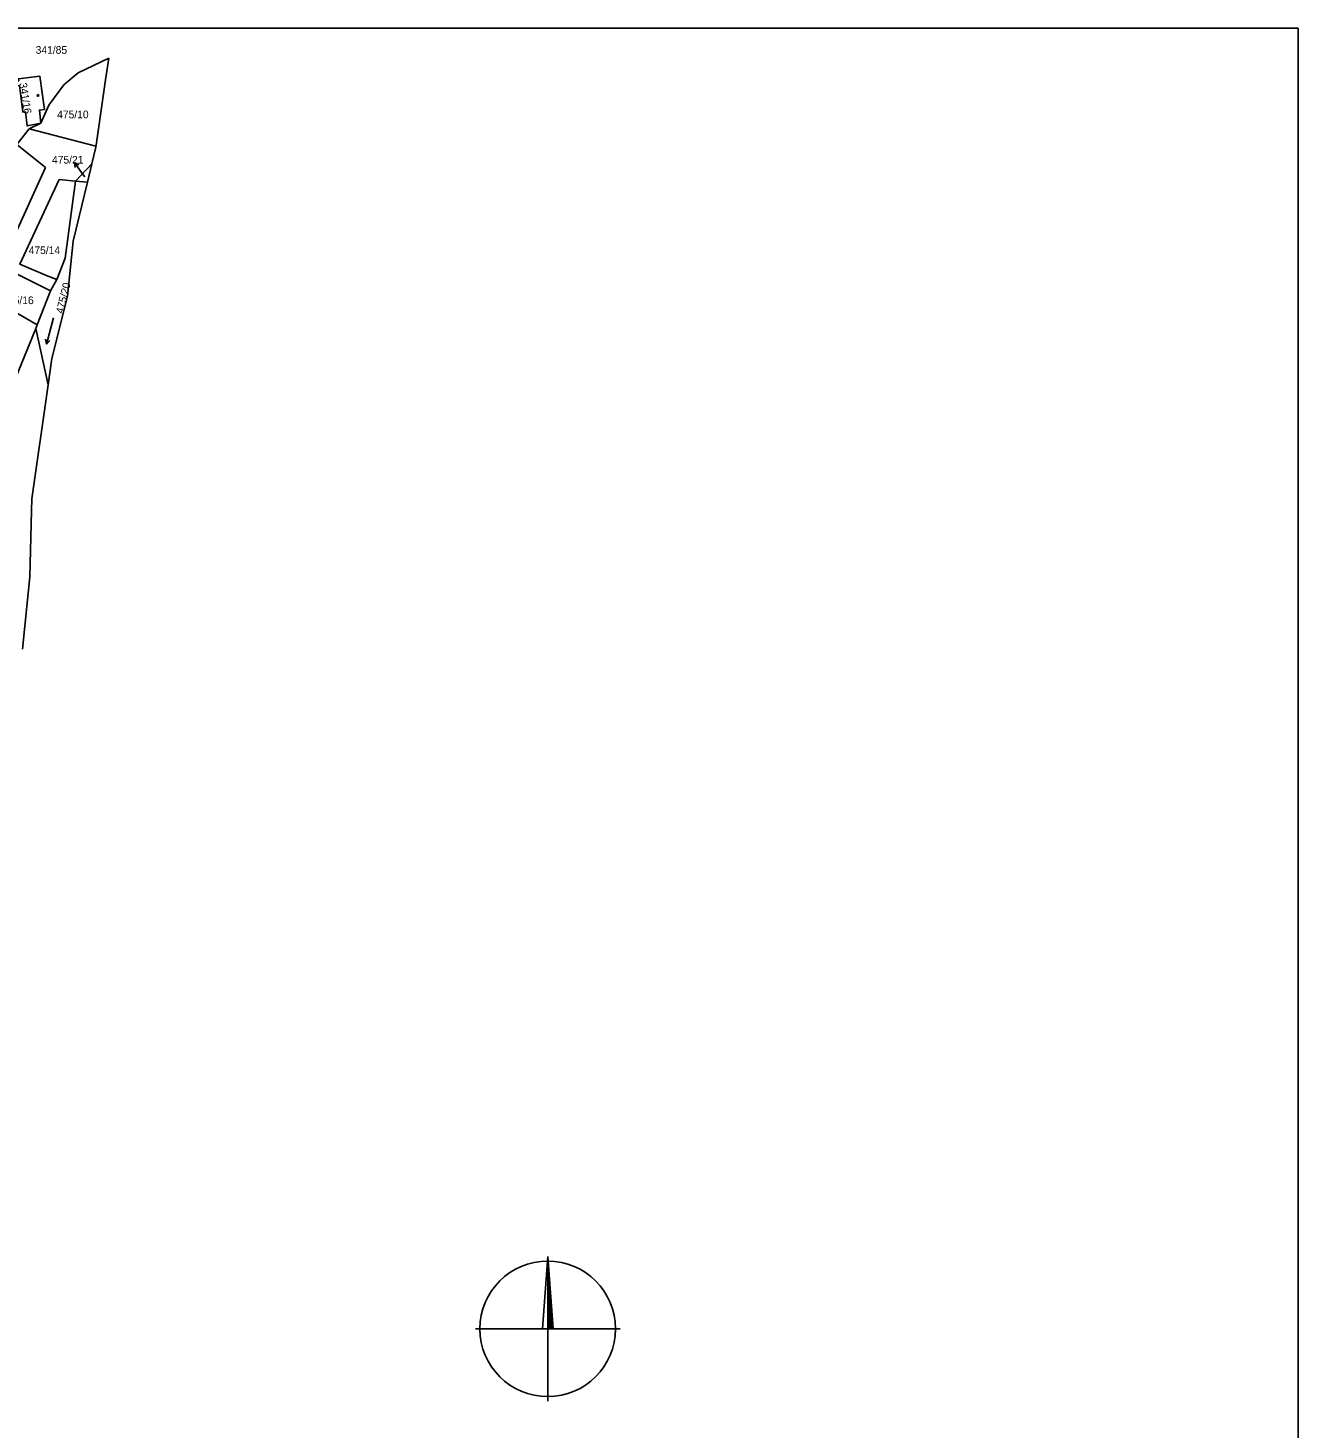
# Model space of a CAD drawing. Extents: x -558358 to -557517, y -1073785 to -1073189.
# Drawn here: x -557797.5 to -557516.5, y -1073499.8 to -1073190.1 of the extents above; entities that cross this region are included whole.
import ezdxf

# ---------------------------------------------------------------- set-up
doc = ezdxf.new("R2010")
doc.units = 0
for name, color, linetype in [('Hranice parcel', 7, 'Continuous'), ('Parcelní čísla', 7, 'Continuous'), ('Pop  PČ popisy', 7, 'Continuous'), ('Vrstva 1', 7, 'Continuous'), ('Značky budov', 7, 'Continuous'), ('Značky kultur', 7, 'Continuous')]:
    doc.layers.add(name, color=color, linetype=linetype)

msp = doc.modelspace()

# ---------------------------------------------------------------- linework, layer by layer
at = {"layer": 'Hranice parcel'}
for p, q in [((-557780.35, -1073201.52), (-557779.66, -1073196.74)), ((-557782.46, -1073216.02), (-557780.35, -1073201.52)), ((-557794.69, -1073211.15), (-557797.26, -1073212.4)), ((-557797.26, -1073212.4), (-557799.96, -1073215.86)), ((-557782.49, -1073216.26), (-557797.26, -1073212.4)), ((-557782.49, -1073216.26), (-557782.46, -1073216.02)), ((-557786.97, -1073223.95), (-557783.4, -1073220.15)), ((-557784.37, -1073224.22), (-557783.4, -1073220.15)), ((-557784.37, -1073224.22), (-557786.97, -1073223.95)), ((-557792.5, -1073248.24), (-557791.11, -1073245.75)), ((-557795.47, -1073255.77), (-557792.5, -1073248.24)), ((-557795.47, -1073255.77), (-557805.42, -1073250.06)), ((-557802.11, -1073272.13), (-557795.8, -1073256.6)), ((-557795.8, -1073256.6), (-557795.47, -1073255.77)), ((-557793.06, -1073269.04), (-557795.8, -1073256.6)), ((-557796.66, -1073294.23), (-557793.06, -1073269.04))]:
    msp.add_line(p, q, dxfattribs=at)
for points in [[(-557779.66, -1073196.74), (-557786.44, -1073199.97), (-557789.57, -1073202.65), (-557792.87, -1073207.17), (-557794.69, -1073211.15)], [(-557794.69, -1073211.15), (-557795, -1073208.24), (-557793.89, -1073208.1), (-557794.86, -1073200.76), (-557799.62, -1073201.3), (-557799.56, -1073201.75), (-557800.39, -1073201.86)], [(-557800.69, -1073202.99), (-557799.42, -1073202.82), (-557798.62, -1073208.73), (-557798.08, -1073208.66), (-557797.7, -1073211.74), (-557794.69, -1073211.15)], [(-557799.96, -1073215.86), (-557793.64, -1073220.96), (-557801.34, -1073237.87)], [(-557783.4, -1073220.15), (-557782.51, -1073216.43), (-557782.49, -1073216.26)], [(-557791.11, -1073245.75), (-557793.29, -1073244.89), (-557799.3, -1073242.34), (-557790.59, -1073223.57), (-557786.97, -1073223.95)], [(-557791.11, -1073245.75), (-557789.25, -1073241.02), (-557786.97, -1073223.95)], [(-557793.06, -1073269.04), (-557792.22, -1073263.19), (-557788.74, -1073249.45), (-557787.48, -1073237.23), (-557784.37, -1073224.22)], [(-557805.42, -1073250.06), (-557802.52, -1073245.72), (-557800.36, -1073244.34), (-557792.5, -1073248.24)], [(-557798.75, -1073327.52), (-557797.09, -1073311.5), (-557796.72, -1073296.93), (-557796.66, -1073294.23)]]:
    msp.add_lwpolyline(points, dxfattribs=at)
at = {"layer": 'Pop  PČ popisy'}
for p, q in [((-557785.49, -1073222.3), (-557787.21, -1073219.84)), ((-557787.21, -1073219.84), (-557786.23, -1073220.38)), ((-557787.21, -1073219.84), (-557787.05, -1073220.95)), ((-557784.97, -1073223.04), (-557785.49, -1073222.3))]:
    msp.add_line(p, q, dxfattribs=at)
at = {"layer": 'Vrstva 1'}
for p, q in [((-558357.53, -1073190.09), (-557516.53, -1073190.09)), ((-557516.53, -1073190.09), (-557516.53, -1073784.09)), ((-557682.53, -1073461.88), (-557683.68, -1073477.88)), ((-557682.53, -1073461.88), (-557681.35, -1073477.88)), ((-557682.53, -1073461.88), (-557682.53, -1073493.88)), ((-557682.43, -1073464.12), (-557681.46, -1073477.78)), ((-557682.4, -1073477.74), (-557682.43, -1073464.12)), ((-557682.36, -1073466.35), (-557681.56, -1073477.71)), ((-557682.29, -1073477.64), (-557682.36, -1073466.35)), ((-557682.26, -1073468.93), (-557681.66, -1073477.57)), ((-557682.22, -1073477.57), (-557682.26, -1073468.93)), ((-557682.15, -1073471.61), (-557681.77, -1073477.46)), ((-557682.12, -1073477.5), (-557682.15, -1073471.61)), ((-557682.01, -1073474.61), (-557681.87, -1073477.29)), ((-557682.01, -1073477.39), (-557682.01, -1073474.61)), ((-557698.53, -1073477.88), (-557666.53, -1073477.88)), ((-557681.35, -1073477.88), (-557682.4, -1073477.74)), ((-557681.46, -1073477.78), (-557682.29, -1073477.64)), ((-557681.56, -1073477.71), (-557682.22, -1073477.57)), ((-557681.66, -1073477.57), (-557682.12, -1073477.5)), ((-557681.77, -1073477.46), (-557682.01, -1073477.39))]:
    msp.add_line(p, q, dxfattribs=at)
msp.add_circle((-557682.53, -1073477.88), 15, dxfattribs=at)
at = {"layer": 'Značky budov'}
msp.add_circle((-557795.31, -1073205.01), 0.175, dxfattribs=at)
at = {"layer": 'Značky kultur'}
for p, q in [((-557791.86, -1073254.23), (-557793.41, -1073260.02)), ((-557793.41, -1073260.02), (-557793.64, -1073258.95)), ((-557793.41, -1073260.02), (-557792.67, -1073259.21))]:
    msp.add_line(p, q, dxfattribs=at)

# ---------------------------------------------------------------- texts
at = {"layer": 'Parcelní čísla'}
for s, p in [('341/85', (-557795.81, -1073195.79)), ('475/10', (-557791.05, -1073210.06)), ('475/21', (-557792.2, -1073220.09)), ('475/14', (-557797.36, -1073240.1)), ('475/16', (-557803.2, -1073251.18))]:
    msp.add_text(s, height=1.7, dxfattribs=at).set_placement(p)
for s, rotation, p in [('341/16', 279, (-557799.46, -1073202.33)), ('475/20', 76, (-557789.74, -1073253.41))]:
    msp.add_text(s, height=1.7, rotation=rotation, dxfattribs=at).set_placement(p)

doc.saveas('drawing.dxf')
